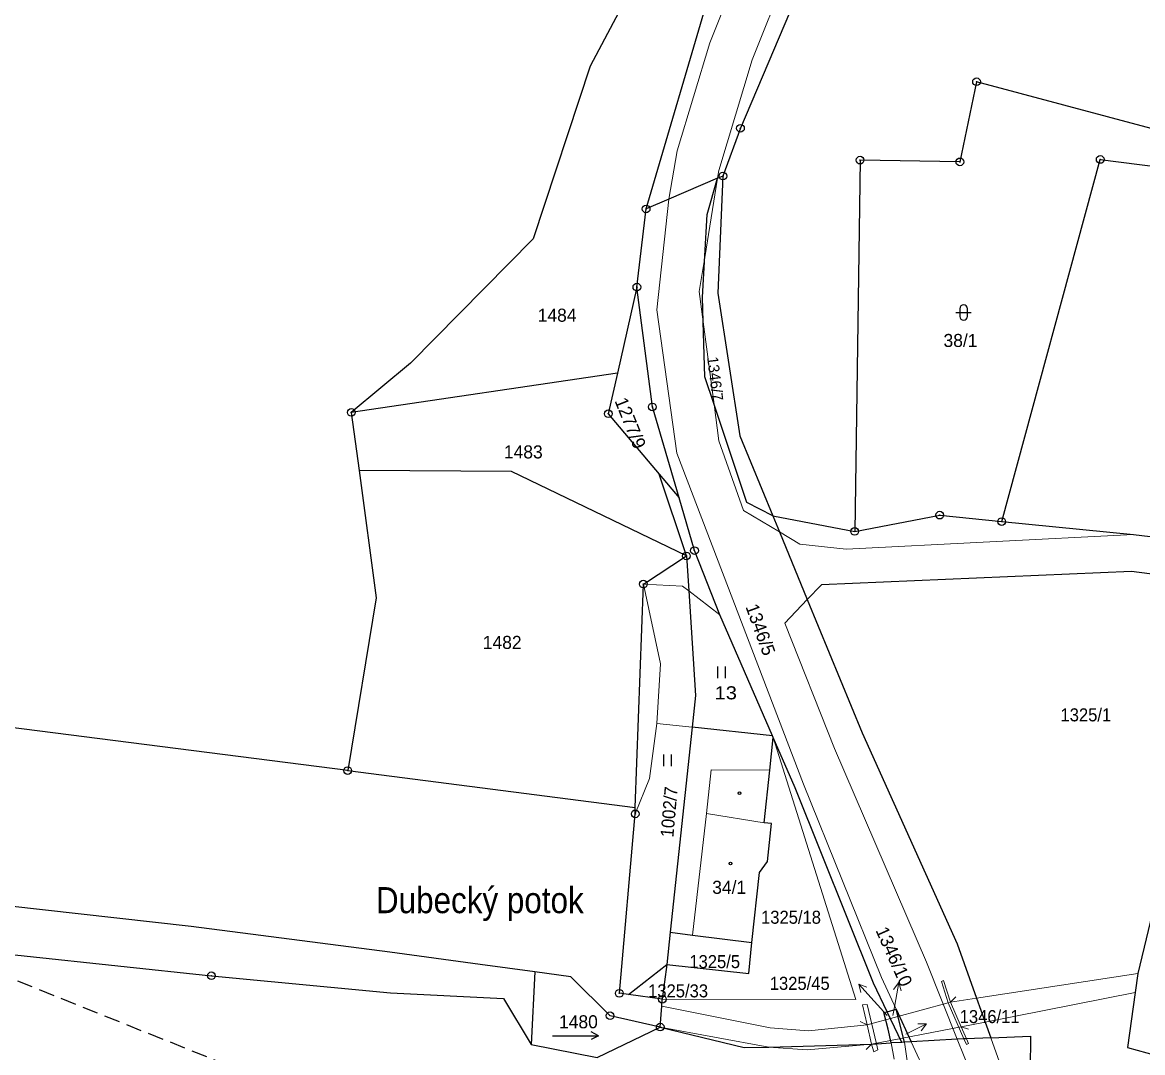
# Model space of a CAD drawing. Extents: x -872229 to -869198, y -1075981 to -1074329.
# Drawn here: x -871207 to -871061.1, y -1075218 to -1075083.8 of the extents above; entities that cross this region are included whole.
import ezdxf
from ezdxf.enums import TextEntityAlignment as Align

# ---------------------------------------------------------------- set-up
doc = ezdxf.new("R2010")
doc.units = 0
doc.header["$LTSCALE"] = 0.68
doc.linetypes.add('MEDIUM_DASHED', pattern=[4.5, 3, -1.5])
for name, color, linetype, lineweight in [('1', 7, 'Continuous', 25), ('3', 7, 'Continuous', 25), ('4', 7, 'Continuous', 13), ('5', 7, 'Continuous', 25), ('6', 7, 'Continuous', 25), ('7', 7, 'Continuous', 13), ('8', 7, 'Continuous', 25)]:
    doc.layers.add(name, color=color, linetype=linetype, lineweight=lineweight)
doc.layers.add('2', color=7, linetype='Continuous')

msp = doc.modelspace()

# ---------------------------------------------------------------- linework, layer by layer
at = {"layer": '1'}
for p, q in [((-871126.95, -1075118.28), (-871125.74, -1075108.09)), ((-871124.04, -1075142.67), (-871121.45, -1075145.75)), ((-871120.49, -1075153.3), (-871124.04, -1075142.67)), ((-871122.61, -1075202.33), (-871123.06, -1075206.55)), ((-871128.02, -1075210.46), (-871123.06, -1075206.55)), ((-871123.06, -1075206.55), (-871123.63, -1075211.06)), ((-871092.41, -1075216.68), (-871094.34, -1075212.69)), ((-871092.1, -1075216.66), (-871093.16, -1075212.36)), ((-871091.2, -1075216.61), (-871092.1, -1075216.66))]:
    msp.add_line(p, q, dxfattribs=at)
for points in [[(-871125.74, -1075108.09), (-871117.37, -1075079.56), (-871098, -1075028.09)], [(-871096.99, -1075058.79), (-871113.45, -1075097.58), (-871115.74, -1075103.81)], [(-871124.45, -1075073.24), (-871133.02, -1075089.5), (-871140.45, -1075111.97), (-871156.44, -1075128.18), (-871164.16, -1075134.61)], [(-871054.49, -1075088.37), (-871056.71, -1075087.82), (-871059.95, -1075097.6), (-871082.7, -1075091.52), (-871084.87, -1075101.96), (-871097.87, -1075101.74), (-871098.57, -1075150.11)], [(-871079.42, -1075148.83), (-871066.59, -1075101.65), (-871036.85, -1075105.44)], [(-871116.43, -1075104.1), (-871122.77, -1075106.82), (-871125.74, -1075108.09)], [(-871109.24, -1075148.09), (-871112.62, -1075146.34), (-871116.89, -1075133.59), (-871118.1, -1075129.96), (-871118.31, -1075122.79), (-871118.41, -1075119.59), (-871117.78, -1075108.8), (-871116.43, -1075104.1)], [(-871115.74, -1075103.81), (-871116.41, -1075104.1), (-871116.43, -1075104.1)], [(-871115.74, -1075103.81), (-871116.38, -1075119.08), (-871113.54, -1075137.64), (-871109.24, -1075148.09), (-871098.57, -1075150.11)], [(-871079.42, -1075148.83), (-871062.25, -1075150.52), (-871046.01, -1075152.47), (-871037.58, -1075154.42), (-871036.85, -1075105.44)], [(-871121.45, -1075145.75), (-871124.93, -1075133.89), (-871126.95, -1075118.28), (-871129.49, -1075129.5)], [(-871129.49, -1075129.5), (-871164.16, -1075134.61), (-871163.14, -1075142.16)], [(-871129.49, -1075129.5), (-871130.67, -1075134.78), (-871124.04, -1075142.67)], [(-871163.14, -1075142.16), (-871160.9, -1075158.75), (-871164.62, -1075181.27), (-871127.17, -1075186.06)], [(-871120.49, -1075153.3), (-871143.29, -1075142.31), (-871163.14, -1075142.16)], [(-871109.26, -1075176.73), (-871116.14, -1075160.96), (-871119.44, -1075152.61), (-871121.45, -1075145.75)], [(-871098.57, -1075150.11), (-871087.49, -1075147.99), (-871079.42, -1075148.83)], [(-871164.62, -1075181.27), (-871265.65, -1075168.37), (-871373.25, -1075154.62), (-871412.02, -1075149.67), (-871424.63, -1075148.05)], [(-871109.24, -1075148.09), (-871108.38, -1075150.17), (-871104.75, -1075159)], [(-871127.17, -1075186.06), (-871126.1, -1075156.97), (-871120.49, -1075153.3)], [(-871120.49, -1075153.3), (-871120.19, -1075157.85), (-871119.29, -1075171.49), (-871119.73, -1075175.61)], [(-870920.27, -1075200.54), (-870931.8, -1075197.32), (-870942.08, -1075192.95), (-870971.72, -1075177.36), (-871005.41, -1075167.04), (-871047.1, -1075157.35), (-871062.52, -1075155.35), (-871102.88, -1075157.06), (-871104.75, -1075159), (-871097.61, -1075176.34), (-871085.24, -1075203.86)], [(-871109.2, -1075176.94), (-871109.26, -1075176.73), (-871119.73, -1075175.61), (-871122.61, -1075202.33), (-871119.69, -1075202.71), (-871111.95, -1075203.66)], [(-871111.95, -1075203.66), (-871110.99, -1075194.53), (-871109.95, -1075193.13), (-871109.41, -1075188.17), (-871110.36, -1075188.06), (-871109.64, -1075181.21), (-871109.2, -1075176.94)], [(-871094.34, -1075212.69), (-871096.14, -1075208.96), (-871106.32, -1075183.51), (-871109.2, -1075176.94)], [(-871001.53, -1075179.18), (-871004.71, -1075177.87), (-871056.06, -1075184.2), (-871061.68, -1075207.72), (-871062.03, -1075210.19), (-871063.04, -1075217.35), (-871059.26, -1075218.39), (-871047.62, -1075220.14), (-871017.06, -1075226.57)], [(-871128.02, -1075210.46), (-871129.23, -1075210.29), (-871127.16, -1075186.91), (-871127.17, -1075186.06)], [(-871140.23, -1075207.5), (-871147.35, -1075206.55), (-871159.14, -1075204.95), (-871185.02, -1075201.57), (-871218.75, -1075197.81)], [(-871219.01, -1075204.11), (-871182.37, -1075208), (-871159.03, -1075210.24), (-871144.33, -1075210.97), (-871140.73, -1075216.95)], [(-871123.06, -1075206.55), (-871112.34, -1075207.69), (-871111.95, -1075203.66)], [(-871085.24, -1075203.86), (-871082.7, -1075210.94), (-871081.59, -1075214.04), (-871080.85, -1075216.08)], [(-871123.91, -1075214.69), (-871130.44, -1075213.21), (-871135.53, -1075208.13), (-871140.23, -1075207.5), (-871140.73, -1075216.95)], [(-871123.91, -1075214.69), (-871123.7, -1075211.96), (-871123.63, -1075211.06), (-871128.02, -1075210.46)], [(-871094.22, -1075214.97), (-871094.76, -1075212.8), (-871094.34, -1075212.69)], [(-871094.34, -1075212.69), (-871093.16, -1075212.36), (-871091.2, -1075216.61)], [(-871140.73, -1075216.95), (-871132.14, -1075218.66), (-871123.91, -1075214.69)], [(-871123.91, -1075214.69), (-871112.99, -1075217.35), (-871109.77, -1075217.3), (-871096.36, -1075216.91)], [(-871096.36, -1075216.91), (-871095.74, -1075216.87), (-871093.8, -1075216.76), (-871094.22, -1075214.97)], [(-871080.85, -1075216.08), (-871084.02, -1075216.21), (-871084.34, -1075216.22), (-871085.21, -1075216.27), (-871091.2, -1075216.61)], [(-871080.85, -1075216.08), (-871075.68, -1075215.86), (-871075.69, -1075220.23), (-871047.62, -1075220.14)], [(-871092.1, -1075216.66), (-871092.41, -1075216.68), (-871093.8, -1075216.76)]]:
    msp.add_lwpolyline(points, dxfattribs=at)
at = {"layer": '3'}
for p, q in [((-871085.391, -1075121.591), (-871083.389, -1075121.591)), ((-871084.891, -1075121.091), (-871084.891, -1075122.092)), ((-871083.889, -1075122.092), (-871083.889, -1075121.091)), ((-871116.411, -1075169.23), (-871116.411, -1075167.73)), ((-871115.41, -1075169.23), (-871115.41, -1075167.73)), ((-871123.431, -1075180.69), (-871123.431, -1075179.19)), ((-871122.43, -1075180.69), (-871122.43, -1075179.19)), ((-871131.933, -1075215.829), (-871132.91, -1075216.33))]:
    msp.add_line(p, q, dxfattribs=at)
msp.add_lwpolyline([(-871137.933, -1075215.829), (-871131.933, -1075215.829), (-871132.91, -1075215.327)], dxfattribs=at)
for centre, start, end in [((-871084.39, -1075121.0909), 0, 180), ((-871084.39, -1075122.0909), 180, 359.98789)]:
    msp.add_arc(centre, 0.5, start, end, dxfattribs=at)
at = {"layer": '4'}
for p, q in [((-871121.71, -1075100.52), (-871117.44, -1075086.44)), ((-871122.77, -1075106.82), (-871121.71, -1075100.52)), ((-871124.35, -1075121.24), (-871122.77, -1075106.82)), ((-871118.83, -1075118.87), (-871118.11, -1075114.44)), ((-871118.83, -1075118.87), (-871118.31, -1075122.79)), ((-871124.35, -1075121.24), (-871121.72, -1075139.93)), ((-871116.26, -1075138.33), (-871113.05, -1075147.37)), ((-871121.72, -1075139.93), (-871105.23, -1075183.06)), ((-871113.05, -1075147.37), (-871108.38, -1075150.17)), ((-871108.38, -1075150.17), (-871105.73, -1075151.76)), ((-871099.7, -1075152.44), (-871062.25, -1075150.52)), ((-871105.73, -1075151.76), (-871099.7, -1075152.44)), ((-871126.1, -1075156.97), (-871123.88, -1075167.38)), ((-871126.1, -1075156.97), (-871120.99, -1075157.24)), ((-871107.69, -1075162.06), (-871104.75, -1075159)), ((-871107.69, -1075162.06), (-871101.22, -1075178.38)), ((-871124.35, -1075175.12), (-871123.88, -1075167.38)), ((-871125.31, -1075182.31), (-871124.35, -1075175.12)), ((-871124.35, -1075175.12), (-871119.73, -1075175.61)), ((-871109.2, -1075176.94), (-871098.43, -1075211.1)), ((-871101.22, -1075178.38), (-871089.2, -1075206.25)), ((-871127.16, -1075186.91), (-871125.31, -1075182.31)), ((-871105.23, -1075183.06), (-871095.06, -1075208.25)), ((-871119.69, -1075202.71), (-871117.87, -1075186.88)), ((-871117.87, -1075186.88), (-871110.36, -1075188.06)), ((-871089.2, -1075206.25), (-871085.21, -1075216.27)), ((-871082.7, -1075210.94), (-871061.68, -1075207.72)), ((-871095.06, -1075208.25), (-871093.16, -1075212.36)), ((-871087.28, -1075208.73), (-871086.99, -1075208.64)), ((-871087.28, -1075208.73), (-871086.38, -1075211.55)), ((-871086.99, -1075208.64), (-871086.09, -1075211.46)), ((-871085.382, -1075210.753), (-871086.089, -1075211.46)), ((-871081.59, -1075214.04), (-871062.03, -1075210.19)), ((-871123.7, -1075211.96), (-871109.59, -1075214.81)), ((-871123.63, -1075211.06), (-871098.43, -1075211.1)), ((-871097.55, -1075211.81), (-871096.93, -1075211.74)), ((-871096.93, -1075211.74), (-871095.74, -1075216.87)), ((-871086.38, -1075211.55), (-871084.34, -1075216.22)), ((-871086.09, -1075211.46), (-871082.7, -1075210.94)), ((-871086.09, -1075211.46), (-871084.69, -1075214.65)), ((-871123.91, -1075214.69), (-871109.77, -1075217.3)), ((-871109.59, -1075214.81), (-871104.57, -1075215.17)), ((-871104.57, -1075215.17), (-871096.95, -1075214.41)), ((-871097.841, -1075213.955), (-871096.95, -1075214.409)), ((-871096.36, -1075216.91), (-871084.69, -1075214.65)), ((-871084.69, -1075214.65), (-871081.59, -1075214.04)), ((-871084.69, -1075214.65), (-871084.02, -1075216.21)), ((-871083.739, -1075214.96), (-871084.69, -1075214.651)), ((-871091.2, -1075216.61), (-871089.08, -1075221.2)), ((-871085.21, -1075216.27), (-871083.4, -1075220.8)), ((-871084.34, -1075216.22), (-871084.02, -1075216.96)), ((-871084.02, -1075216.21), (-871083.74, -1075216.84)), ((-871080.85, -1075216.08), (-871079.27, -1075220.49)), ((-871109.77, -1075217.3), (-871104.75, -1075217.66)), ((-871104.75, -1075217.66), (-871096.36, -1075216.91)), ((-871097.068, -1075217.617), (-871096.361, -1075216.91)), ((-871095.74, -1075216.87), (-871095.56, -1075217.65)), ((-871093.8, -1075216.76), (-871093.43, -1075218.88)), ((-871092.1, -1075216.66), (-871091.39, -1075221.36)), ((-871084.02, -1075216.96), (-871083.74, -1075216.84))]:
    msp.add_line(p, q, dxfattribs=at)
for points in [[(-871117.44, -1075086.44), (-871104.3, -1075053.55), (-871091.42, -1075021.56)], [(-871098.77, -1075055.79), (-871111.92, -1075088.68), (-871116.26, -1075103.1)], [(-871118.11, -1075114.44), (-871116.43, -1075104.1), (-871116.26, -1075103.1)], [(-871118.31, -1075122.79), (-871116.89, -1075133.59), (-871116.26, -1075138.33)], [(-871120.99, -1075157.24), (-871120.19, -1075157.85), (-871116.14, -1075160.96)], [(-871117.87, -1075186.88), (-871117.29, -1075181.19), (-871109.64, -1075181.21)], [(-871097.55, -1075211.81), (-871096.95, -1075214.41), (-871096.36, -1075216.91)], [(-871096.95, -1075214.41), (-871086.38, -1075211.55), (-871086.09, -1075211.46)], [(-871096.36, -1075216.91), (-871096.07, -1075217.9), (-871095.56, -1075217.65)]]:
    msp.add_lwpolyline(points, dxfattribs=at)
at = {"layer": '5'}
for centre in [(-871113.5868, -1075184.2092), (-871114.7368, -1075193.3692)]:
    msp.add_circle(centre, 0.175, dxfattribs=at)
at = {"layer": '6', "linetype": 'MEDIUM_DASHED'}
msp.add_line((-871219.01, -1075204.11), (-871164.94, -1075225.78), dxfattribs=at)
at = {"layer": '7'}
for p, q in [((-871098.048, -1075209.1), (-871097.75, -1075210.179)), ((-871092.839, -1075208.875), (-871093.506, -1075209.774)), ((-871089.236, -1075214.258), (-871090.356, -1075214.266))]:
    msp.add_line(p, q, dxfattribs=at)
for points in [[(-871094.36, -1075213.18), (-871096.04, -1075211.33), (-871098.048, -1075209.1), (-871097.006, -1075209.509)], [(-871093.61, -1075213.2), (-871093.36, -1075211.83), (-871092.839, -1075208.875), (-871092.52, -1075209.948)], [(-871091.91, -1075215.62), (-871089.236, -1075214.258), (-871089.901, -1075215.158)]]:
    msp.add_lwpolyline(points, dxfattribs=at)
at = {"layer": '8'}
for centre, radius in [((-871082.7, -1075091.5199), 0.5), ((-871082.7, -1075091.5199), 0.0303), ((-871113.45, -1075097.5799), 0.5), ((-871113.45, -1075097.5799), 0.0303), ((-871097.87, -1075101.7399), 0.5), ((-871066.59, -1075101.6499), 0.5), ((-871097.87, -1075101.7399), 0.0303), ((-871084.87, -1075101.9599), 0.5), ((-871084.87, -1075101.9599), 0.0303), ((-871066.59, -1075101.6499), 0.0303), ((-871115.74, -1075103.8099), 0.5), ((-871115.74, -1075103.8099), 0.0303), ((-871125.74, -1075108.0899), 0.5), ((-871125.74, -1075108.0899), 0.0303), ((-871126.95, -1075118.2799), 0.5), ((-871126.95, -1075118.2799), 0.0303), ((-871124.93, -1075133.8899), 0.5), ((-871164.16, -1075134.6099), 0.5), ((-871164.16, -1075134.6099), 0.0303), ((-871130.67, -1075134.7799), 0.5), ((-871130.67, -1075134.7799), 0.0303), ((-871124.93, -1075133.8899), 0.0303), ((-871087.49, -1075147.9899), 0.5), ((-871087.49, -1075147.9899), 0.0303), ((-871079.42, -1075148.8299), 0.5), ((-871079.42, -1075148.8299), 0.0303), ((-871098.57, -1075150.1099), 0.5), ((-871098.57, -1075150.1099), 0.0303), ((-871119.44, -1075152.6099), 0.5), ((-871120.49, -1075153.2999), 0.5), ((-871120.49, -1075153.2999), 0.0303), ((-871119.44, -1075152.6099), 0.0303), ((-871126.1, -1075156.9699), 0.5), ((-871126.1, -1075156.9699), 0.0303), ((-871164.62, -1075181.2699), 0.5), ((-871164.62, -1075181.2699), 0.0303), ((-871127.16, -1075186.9099), 0.5), ((-871127.16, -1075186.9099), 0.0303), ((-871182.37, -1075207.9999), 0.5), ((-871182.37, -1075207.9999), 0.0303), ((-871129.23, -1075210.2899), 0.5), ((-871129.23, -1075210.2899), 0.0303), ((-871123.63, -1075211.0599), 0.5), ((-871123.63, -1075211.0599), 0.0303), ((-871130.44, -1075213.2099), 0.5), ((-871130.44, -1075213.2099), 0.0303), ((-871123.91, -1075214.6899), 0.5), ((-871123.91, -1075214.6899), 0.0303)]:
    msp.add_circle(centre, radius, dxfattribs=at)

# ---------------------------------------------------------------- texts
at = {"layer": '2'}
for s, p in [('1484', (-871139.87, -1075122.79)), ('38/1', (-871087, -1075126.08)), ('1483', (-871144.27, -1075140.6)), ('1482', (-871147.02, -1075165.42)), ('34/1', (-871117.13, -1075197.33)), ('1480', (-871137.09, -1075214.85))]:
    msp.add_text(s, height=1.7, dxfattribs=at).set_placement(p)
for s, height, rotation, p in [('1346/7', 1.418, 277, (-871117.4459, -1075130.2931)), ('1346/10', 1.7, 294, (-871094.2133, -1075205.8358))]:
    msp.add_text(s, height=height, rotation=rotation, dxfattribs=at).set_placement(p, align=Align.CENTER)
for s, rotation, p in [('1277/9', 292, (-871129.878, -1075133.088)), ('1346/5', 290, (-871112.818, -1075159.92))]:
    msp.add_text(s, height=1.7, rotation=rotation, dxfattribs=at).set_placement(p)
for s, width, p in [('13', 1.15, (-871116.82, -1075171.99)), ('1325/1', 0.95, (-871071.76, -1075174.86)), ('1325/18', 0.95, (-871110.77, -1075201.23)), ('1325/5', 0.95, (-871120.11, -1075207.01)), ('1325/33', 0.95, (-871125.48, -1075210.82))]:
    msp.add_text(s, height=1.7, dxfattribs=dict(at, width=width)).set_placement(p)
at = {"layer": '2', "width": 0.95}
msp.add_text('1002/7', height=1.7, rotation=85, dxfattribs=at).set_placement((-871122.193, -1075190.024))
for s, p in [('1325/45', (-871105.73, -1075209.84)), ('1346/11', (-871080.99, -1075214.17))]:
    msp.add_text(s, height=1.7, dxfattribs=at).set_placement(p, align=Align.CENTER)
at = {"layer": '7', "width": 0.9}
msp.add_text('Dubecký potok', height=3.4, dxfattribs=at).set_placement((-871160.94, -1075199.85))

doc.saveas('drawing.dxf')
